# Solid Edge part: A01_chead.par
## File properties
Author: mokuno
Template: metric.par
Last saved by: edge
Revision: 61
Application: Solid Edge
Material: 鋼鉄, 鋼材
面のスタイル: Steel
塗りつぶしのスタイル: ANSI32(Steel)
バーチャルスタイル: 鋼鉄 ブラシ
Coef. of Thermal Exp: 0.0
Thermal Conductivity: 32.0
Specific Heat: 481.0
Modulus of Elasticity: 199947953000.0
Poisson's Ratio: 0.29
Yield Stress: 262000766.0
Ultimate Stress: 358527364.0
Elongation: 0.0
File Size: 0
Number of Sheets: 0
Number of Objects: 0
非切断部品: False
文書内容のタイプ: 0
Density: 7702
Accuracy: 0.00
Document Number: C-3701
Revision: 1
Project Name: Trolley Wheel Assembly
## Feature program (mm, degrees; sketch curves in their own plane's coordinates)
sketch for "ExtrudedProtrusion_1" plane through (0, 0, 0) normal (0, -1, 0) x-axis (1, 0, 0)
  line (-60, 25) -> (60, 25)
  line (60, 25) -> (60, -25)
  line (60, -25) -> (-60, -25)
  line (-60, -25) -> (-60, 25)
  dimension (linear) = 60
  dimension (linear) = 60
extrude "ExtrudedProtrusion_1" add finite 140 symmetric
sketch for "unnamed Hole 1" plane through (6.6875, 70, -3.9886) normal (0, 1, 0) x-axis (-1, 0, 0)
  hole centre (36.6875, 3.9886) bore radius 10
hole "unnamed Hole 1" through
sketch for "unnamed Hole 2" plane through (6.6875, 70, -3.9886) normal (0, 1, 0) x-axis (-1, 0, 0)
  hole centre (-23.3125, 3.9886) bore radius 10
hole "unnamed Hole 2" through
pattern "unnamed Pattern 1" of "unnamed Hole 1", "unnamed Hole 2"
sketch for "Hole_3" plane through (6.6875, 70, 25) normal (0, 0, 1) x-axis (-1, 0, 0)
  hole centre (6.6875, 70) bore radius 10
hole "Hole_3" through  CounterBoreDepth = 12 mm
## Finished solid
Body 1: solid body, 11 faces, 20 edges, 8 vertices.
  Faces by surface: plane 7, cylinder 4
  Edges by curve: line 12, circle 8
Bounding box of the edges (mm): 120.000 x 140.000 x 50.000, from (-60, -70, -25) to (60, 70, 25).
Cylindrical faces by radius (mm): R10 x3, R18 x1
Planar faces by outward normal: +x 1, +y 1, +z 2, -x 1, -y 1, -z 1
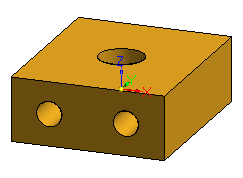
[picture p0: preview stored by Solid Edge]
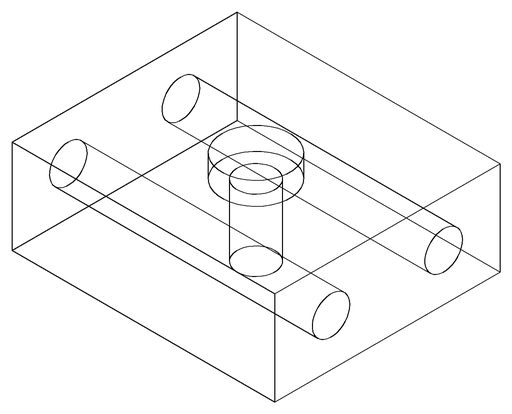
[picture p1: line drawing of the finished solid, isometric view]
